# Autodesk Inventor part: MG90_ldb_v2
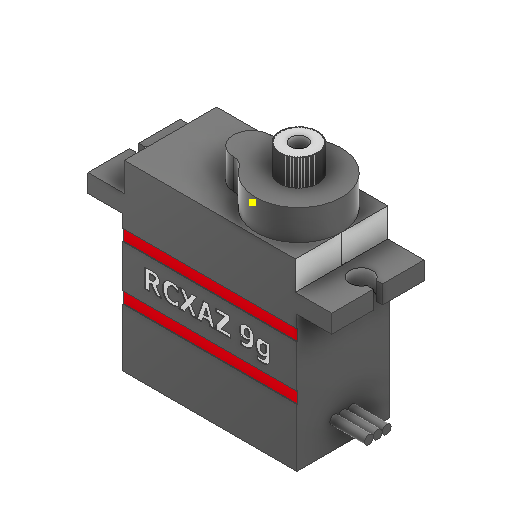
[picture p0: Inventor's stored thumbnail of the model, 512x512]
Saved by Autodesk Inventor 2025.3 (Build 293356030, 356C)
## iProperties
Created: 2019-07
Part Number: MG90_ldb_v2
Material: Steel
Document SubType Name: Modeling
Designer: Ryzen5700u
Density: 7.85 g/cm^3
Appearance: Default
Author: Ryzen5700u
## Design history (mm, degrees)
node "Geometria corretta1"
  node "Schizzo8-Invisible"
node "Solido1"
sketch "Schizzo2-Invisible"
sketch "Schizzo9-Invisible"
node "Schizzo11-Invisible"
node "Schizzo12-Invisible"
node "Schizzo6-Invisible"
sketch "Schizzo10-Invisible"
node "Schizzo7-Invisible"
node "Schizzo13-Invisible"
sketch "Schizzo1"
  geometry: L1 (23, -4.915)-(23, 0) reference; L2 (23, 0)-(0, 0) reference; L3 (0, 0)-(0, -12.5) reference; L4 (0, -12.5)-(23, -12.5) reference; L5 (23, -12.5)-(23, -7.585) reference; A1 r 6 centre (17.15, -6.25) between (23, -4.915) and (11.734, -3.666) reference; A2 r 6 centre (17.15, -6.25) between (11.734, -8.834) and (23, -7.585) reference; A3 r 2.7 centre (10.95, -6.25) between (11.734, -3.666) and (11.734, -8.834) reference; 1 further point
extrude "Estrusione1" join sketch "Schizzo1" distance "d0" = 1.3; taper "d1" = 0 deg
sketch "Schizzo2"
  geometry: L1 (4.6, 0)-(4.6, -12.5) reference; L2 (4.6, 0)-(0, 0) reference; L3 (0, 0)-(0, -5.65) reference; L4 (1.4, -5.65)-(0, -5.65) reference; L5 (1.4, -6.85)-(0, -6.85) reference; L6 (0, -6.85)-(0, -12.5) reference; L7 (4.6, -12.5)-(0, -12.5) reference; L8 (27.6, -12.5)-(27.6, 0) reference; L9 (27.6, -12.5)-(32.2, -12.5) reference; L10 (32.2, -12.5)-(32.2, -6.85) reference; L11 (30.8, -6.85)-(32.2, -6.85) reference; L12 (30.8, -5.65)-(32.2, -5.65) reference; L13 (32.2, -5.65)-(32.2, 0) reference; L14 (27.6, 0)-(32.2, 0) reference; A1 r 1 centre (2.2, -6.25) between (1.4, -6.85) and (1.4, -5.65) reference; A2 r 1 centre (30, -6.25) between (30.8, -5.65) and (30.8, -6.85) reference; 1 further point
extrude "Estrusione2" cut sketch "Schizzo2" distance "d5" = 1.8; taper "d6" = 0 deg
sketch "Schizzo3"
  geometry: L1 (4.6, 0)-(4.6, -12.5) reference; L2 (4.6, 0)-(0, 0) reference; L3 (0, 0)-(0, -5.65) reference; L4 (0, -5.65)-(1.4, -5.65) reference; L5 (1.4, -6.85)-(0, -6.85) reference; L6 (0, -6.85)-(0, -12.5) reference; L7 (4.6, -12.5)-(0, -12.5) reference; L8 (27.6, -12.5)-(27.6, 0) reference; L9 (27.6, -12.5)-(32.2, -12.5) reference; L10 (32.2, -12.5)-(32.2, -6.85) reference; L11 (32.2, -6.85)-(30.8, -6.85) reference; L12 (30.8, -5.65)-(32.2, -5.65) reference; L13 (32.2, -5.65)-(32.2, 0) reference; L14 (27.6, 0)-(32.2, 0) reference; A1 r 1 centre (2.2, -6.25) between (1.4, -6.85) and (1.4, -5.65) reference; A2 r 1 centre (30, -6.25) between (30.8, -5.65) and (30.8, -6.85) reference; 1 further point
extrude "Estrusione3" join sketch "Schizzo3" distance "d7" = 1.5; taper "d8" = 0 deg
sketch "Schizzo4"
  geometry: L1 (-0.548, -2.337)-(-0.45, -2.358) reference; L2 (-0.569, -2.434)-(-0.548, -2.337) reference; L3 (-0.694, -2.298)-(-0.725, -2.393) reference; L4 (-0.789, -2.267)-(-0.694, -2.298) reference; L5 (-0.82, -2.362)-(-0.789, -2.267) reference; L6 (-0.93, -2.213)-(-0.971, -2.304) reference; L7 (-1.022, -2.172)-(-0.93, -2.213) reference; L8 (-1.062, -2.263)-(-1.022, -2.172) reference; L9 (-1.157, -2.103)-(-1.206, -2.19) reference; L10 (-1.243, -2.053)-(-1.157, -2.103) reference; L11 (-1.293, -2.14)-(-1.243, -2.053) reference; L12 (-1.37, -1.971)-(-1.429, -2.052) reference; L13 (-1.451, -1.912)-(-1.37, -1.971) reference; L14 (-1.51, -1.993)-(-1.451, -1.912) reference; L15 (-1.569, -1.817)-(-1.635, -1.891) reference; L16 (-1.643, -1.75)-(-1.569, -1.817) reference; L17 (-1.71, -1.824)-(-1.643, -1.75) reference; L18 (-1.75, -1.643)-(-1.824, -1.71) reference; L19 (-1.817, -1.569)-(-1.75, -1.643) reference; L20 (-1.891, -1.635)-(-1.817, -1.569) reference; L21 (-1.912, -1.451)-(-1.993, -1.51) reference; L22 (-1.971, -1.37)-(-1.912, -1.451) reference; L23 (-2.052, -1.429)-(-1.971, -1.37) reference; L24 (-2.053, -1.243)-(-2.14, -1.293) reference; L25 (-2.103, -1.157)-(-2.053, -1.243) reference; L26 (-2.19, -1.206)-(-2.103, -1.157) reference; L27 (-2.172, -1.022)-(-2.263, -1.062) reference; L28 (-2.213, -0.93)-(-2.172, -1.022) reference; L29 (-2.304, -0.971)-(-2.213, -0.93) reference; L30 (-2.267, -0.789)-(-2.362, -0.82) reference; L31 (-2.298, -0.694)-(-2.267, -0.789) reference; L32 (-2.393, -0.725)-(-2.298, -0.694) reference; L33 (-2.337, -0.548)-(-2.434, -0.569) reference; L34 (-2.358, -0.45)-(-2.337, -0.548) reference; L35 (-2.455, -0.471)-(-2.358, -0.45) reference; L36 (-2.382, -0.301)-(-2.481, -0.311) reference; L37 (-2.392, -0.201)-(-2.382, -0.301) reference; L38 (-2.491, -0.212)-(-2.392, -0.201) reference; L39 (-2.4, -0.05)-(-2.499, -0.05) reference; L40 (-2.4, 0.05)-(-2.4, -0.05) reference; L41 (-2.499, 0.05)-(-2.4, 0.05) reference; L42 (-2.392, 0.201)-(-2.491, 0.212) reference; L43 (-2.382, 0.301)-(-2.392, 0.201) reference; L44 (-2.481, 0.311)-(-2.382, 0.301) reference; L45 (-2.358, 0.45)-(-2.455, 0.471) reference; L46 (-2.337, 0.548)-(-2.358, 0.45) reference; L47 (-2.434, 0.569)-(-2.337, 0.548) reference; L48 (-2.298, 0.694)-(-2.393, 0.725) reference; L49 (-2.267, 0.789)-(-2.298, 0.694) reference; L50 (-2.362, 0.82)-(-2.267, 0.789) reference; L51 (-2.213, 0.93)-(-2.304, 0.971) reference; L52 (-2.172, 1.022)-(-2.213, 0.93) reference; L53 (-2.263, 1.062)-(-2.172, 1.022) reference; L54 (-2.103, 1.157)-(-2.19, 1.206) reference; L55 (-2.053, 1.243)-(-2.103, 1.157) reference; L56 (-2.14, 1.293)-(-2.053, 1.243) reference; L57 (-1.971, 1.37)-(-2.052, 1.429) reference; L58 (-1.912, 1.451)-(-1.971, 1.37) reference; L59 (-1.993, 1.51)-(-1.912, 1.451) reference; L60 (-1.817, 1.569)-(-1.891, 1.635) reference; L61 (-1.75, 1.643)-(-1.817, 1.569) reference; L62 (-1.824, 1.71)-(-1.75, 1.643) reference; L63 (-1.643, 1.75)-(-1.71, 1.824) reference; L64 (-1.569, 1.817)-(-1.643, 1.75) reference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; A1 r 6 centre (0, 0) between (-5.416, -2.584) and (-5.416, 2.584) reference; A2 r 2.7 centre (-6.2, 0) between (-5.416, 2.584) and (-5.416, -2.584) reference; A3 r 2.5 centre (0, 0) between (-0.725, -2.393) and (-0.569, -2.434) reference; A4 r 2.5 centre (0, 0) between (-0.971, -2.304) and (-0.82, -2.362) reference; A5 r 2.5 centre (0, 0) between (-1.206, -2.19) and (-1.062, -2.263) reference; A6 r 2.5 centre (0, 0) between (-1.429, -2.052) and (-1.293, -2.14) reference; A7 r 2.5 centre (0, 0) between (-1.635, -1.891) and (-1.51, -1.993) reference; A8 r 2.5 centre (0, 0) between (-1.824, -1.71) and (-1.71, -1.824) reference; A9 r 2.5 centre (0, 0) between (-1.993, -1.51) and (-1.891, -1.635) reference; A10 r 2.5 centre (0, 0) between (-2.14, -1.293) and (-2.052, -1.429) reference; A11 r 2.5 centre (0, 0) between (-2.263, -1.062) and (-2.19, -1.206) reference; A12 r 2.5 centre (0, 0) between (-2.362, -0.82) and (-2.304, -0.971) reference; A13 r 2.5 centre (0, 0) between (-2.434, -0.569) and (-2.393, -0.725) reference; A14 r 2.5 centre (0, 0) between (-2.481, -0.311) and (-2.455, -0.471) reference; A15 r 2.5 centre (0, 0) between (-2.499, -0.05) and (-2.491, -0.212) reference; A16 r 2.5 centre (0, 0) between (-2.491, 0.212) and (-2.499, 0.05) reference; A17 r 2.5 centre (0, 0) between (-2.455, 0.471) and (-2.481, 0.311) reference; A18 r 2.5 centre (0, 0) between (-2.393, 0.725) and (-2.434, 0.569) reference; A19 r 2.5 centre (0, 0) between (-2.304, 0.971) and (-2.362, 0.82) reference; A20 r 2.5 centre (0, 0) between (-2.19, 1.206) and (-2.263, 1.062) reference; A21 r 2.5 centre (0, 0) between (-2.052, 1.429) and (-2.14, 1.293) reference; A22 r 2.5 centre (0, 0) between (-1.891, 1.635) and (-1.993, 1.51) reference; A23 r 2.5 centre (0, 0) between (-1.71, 1.824) and (-1.824, 1.71) reference; A24 r 2.5 centre (0, 0) between (-1.51, 1.993) and (-1.635, 1.891) reference; A25 r 2.5 centre (0, 0) between (-1.293, 2.14) and (-1.429, 2.052) reference; A26 r 2.5 centre (0, 0) between (-1.062, 2.263) and (-1.206, 2.19) reference; A27 r 2.5 centre (0, 0) between (-0.82, 2.362) and (-0.971, 2.304) reference; A28 r 2.5 centre (0, 0) between (-0.569, 2.434) and (-0.725, 2.393) reference; A29 r 2.5 centre (0, 0) between (-0.311, 2.481) and (-0.471, 2.455) reference; A30 r 2.5 centre (0, 0) between (-0.05, 2.499) and (-0.212, 2.491) reference; A31 r 2.5 centre (0, 0) between (0.212, 2.491) and (0.05, 2.499) reference; A32 r 2.5 centre (0, 0) between (0.471, 2.455) and (0.311, 2.481) reference; A33 r 2.5 centre (0, 0) between (0.725, 2.393) and (0.569, 2.434) reference; A34 r 2.5 centre (0, 0) between (0.971, 2.304) and (0.82, 2.362) reference; A35 r 2.5 centre (0, 0) between (1.206, 2.19) and (1.062, 2.263) reference; A36 r 2.5 centre (0, 0) between (1.429, 2.052) and (1.293, 2.14) reference; A37 r 2.5 centre (0, 0) between (1.635, 1.891) and (1.51, 1.993) reference; A38 r 2.5 centre (0, 0) between (1.824, 1.71) and (1.71, 1.824) reference; A39 r 2.5 centre (0, 0) between (1.993, 1.51) and (1.891, 1.635) reference; A40 r 2.5 centre (0, 0) between (2.14, 1.293) and (2.052, 1.429) reference; A41 r 2.5 centre (0, 0) between (2.263, 1.062) and (2.19, 1.206) reference; A42 r 2.5 centre (0, 0) between (2.362, 0.82) and (2.304, 0.971) reference; A43 r 2.5 centre (0, 0) between (2.434, 0.569) and (2.393, 0.725) reference; A44 r 2.5 centre (0, 0) between (2.481, 0.311) and (2.455, 0.471) reference; A45 r 2.5 centre (0, 0) between (2.499, 0.05) and (2.491, 0.212) reference; A46 r 2.5 centre (0, 0) between (2.491, -0.212) and (2.499, -0.05) reference; A47 r 2.5 centre (0, 0) between (2.455, -0.471) and (2.481, -0.311) reference; A48 r 2.5 centre (0, 0) between (2.393, -0.725) and (2.434, -0.569) reference; A49 r 2.5 centre (0, 0) between (2.304, -0.971) and (2.362, -0.82) reference; A50 r 2.5 centre (0, 0) between (2.19, -1.206) and (2.263, -1.062) reference; A51 r 2.5 centre (0, 0) between (2.052, -1.429) and (2.14, -1.293) reference; A52 r 2.5 centre (0, 0) between (1.891, -1.635) and (1.993, -1.51) reference; A53 r 2.5 centre (0, 0) between (1.71, -1.824) and (1.824, -1.71) reference; A54 r 2.5 centre (0, 0) between (1.51, -1.993) and (1.635, -1.891) reference; A55 r 2.5 centre (0, 0) between (1.293, -2.14) and (1.429, -2.052) reference; A56 r 2.5 centre (0, 0) between (1.062, -2.263) and (1.206, -2.19) reference; A57 r 2.5 centre (0, 0) between (0.82, -2.362) and (0.971, -2.304) reference; A58 r 2.5 centre (0, 0) between (0.569, -2.434) and (0.725, -2.393) reference; A59 r 2.5 centre (0, 0) between (0.311, -2.481) and (0.471, -2.455) reference; A60 r 2.5 centre (0, 0) between (0.05, -2.499) and (0.212, -2.491) reference; A61 r 2.5 centre (0, 0) between (-0.212, -2.491) and (-0.05, -2.499) reference; A62 r 2.5 centre (0, 0) between (-0.471, -2.455) and (-0.311, -2.481) reference; 1 further point
extrude "Estrusione4" cut sketch "Schizzo4" distance "d9" = 0.7; taper "d10" = 0 deg
sketch "Schizzo5"
  geometry: C1 r 1.1 at (0, 0) reference; C2 r 3.334 at (0, 0); 1 further point
  constraints: 1 centre point, 1 coincident
extrude "Estrusione5" cut sketch "Schizzo5" distance "d11" = 1.2; taper "d12" = 0 deg
node "Modifica diretta1"
node "Modifica diretta2"
sketch "Schizzo6"
  geometry: L1 (23, 0)-(23, 17.2) reference; L2 (0, 17.2)-(0, 0) reference; L3 (23, 5.728)-(0, 5.728); L4 (0, 5.728)-(0, 17.02); L5 (0, 17.02)-(23, 17.02); L6 (23, 17.02)-(23, 5.728); 3 further points
  constraints: 8 end point, 2 parallel, 2 point on line, 1 horizontal, 1 perpendicular
extrude "Estrusione6" cut sketch "Schizzo6" distance "d19" = 0.1; taper "d20" = 0 deg
sketch "Schizzo8"
  geometry: L1 (21.235, 0)-(0, 0) reference; L2 (21.235, 12.123)-(21.235, 0) reference; L3 (0, 12.123)-(21.235, 12.123) reference; L4 (0, 0)-(0, 12.123) reference; 1 further point
extrude "Estrusione7" join sketch "Schizzo8" stored distance "d21" = 10; taper "d22" = 0 deg
sketch "Schizzo9"
  geometry: L1 (0, 5.728)-(0, 17.02) reference; L2 (23, 5.728)-(0, 5.728) reference; L3 (23, 17.02)-(23, 5.728) reference; L4 (0, 17.02)-(23, 17.02) reference; 1 further point
extrude "Estrusione8" join sketch "Schizzo9" stored distance "d23" = 10; taper "d24" = 0 deg
sketch "Schizzo10"
  geometry: L1 (23, 0)-(0, 0) reference; L2 (23, 12.5)-(23, 0) reference; L3 (0, 12.5)-(23, 12.5) reference; L4 (0, 0)-(0, 12.5) reference; L5 (-2.4, 6.25)-(30.242, 6.25); L6 (-6.338, 12.35)-(30.57, 12.35); L7 (30.57, 12.35)-(30.57, 0.15); L8 (30.57, 0.15)-(-6.338, 0.15); L9 (-6.338, 0.15)-(-6.338, 12.35); L10 (-4.6, 6.85)-(-3.2, 6.85) reference; L11 (-3.2, 5.65)-(-4.6, 5.65) reference; L12 (-4.6, 5.65)-(-4.6, 0) reference; L13 (-4.6, 0)-(0, 0) reference; L14 (0, 12.5)-(0, 0) reference; L15 (0, 12.5)-(-4.6, 12.5) reference; L16 (-4.6, 12.5)-(-4.6, 6.85) reference; L17 (27.6, 5.65)-(26.2, 5.65) reference; L18 (26.2, 6.85)-(27.6, 6.85) reference; L19 (27.6, 6.85)-(27.6, 12.5) reference; L20 (27.6, 12.5)-(23, 12.5) reference; L21 (23, 0)-(23, 12.5) reference; L22 (23, 0)-(27.6, 0) reference; L23 (27.6, 0)-(27.6, 5.65) reference; A1 r 1 centre (-2.4, 6.25) between (-3.2, 5.65) and (-3.2, 6.85) reference; A2 r 1 centre (-2.4, 6.25) between (-3.2, 5.65) and (-3.2, 6.85) reference; A3 r 1 centre (25.4, 6.25) between (26.2, 6.85) and (26.2, 5.65) reference; 13 further points
  constraints: 10 end point, 2 horizontal, 2 parallel, 1 perpendicular, 1 other
  dimensions: "d28" = 12.2 distance of L8.end L6.start
extrude "Estrusione9" cut sketch "Schizzo10" extent not by distance; stored distance "d29" = 0; taper "d30" = 0 deg
sketch "Schizzo11"
  geometry: L1 (-0.569, -2.434)-(-0.548, -2.337) reference; L2 (-0.694, -2.298)-(-0.725, -2.393) reference; L3 (-0.789, -2.267)-(-0.694, -2.298) reference; L4 (-0.82, -2.362)-(-0.789, -2.267) reference; L5 (-0.93, -2.213)-(-0.971, -2.304) reference; L6 (-1.022, -2.172)-(-0.93, -2.213) reference; L7 (-1.062, -2.263)-(-1.022, -2.172) reference; L8 (-1.157, -2.103)-(-1.206, -2.19) reference; L9 (-1.243, -2.053)-(-1.157, -2.103) reference; L10 (-1.293, -2.14)-(-1.243, -2.053) reference; L11 (-1.37, -1.971)-(-1.429, -2.052) reference; L12 (-1.451, -1.912)-(-1.37, -1.971) reference; L13 (-1.51, -1.993)-(-1.451, -1.912) reference; L14 (-1.569, -1.817)-(-1.635, -1.891) reference; L15 (-1.643, -1.75)-(-1.569, -1.817) reference; L16 (-1.71, -1.824)-(-1.643, -1.75) reference; L17 (-1.75, -1.643)-(-1.824, -1.71) reference; L18 (-1.817, -1.569)-(-1.75, -1.643) reference; L19 (-1.891, -1.635)-(-1.817, -1.569) reference; L20 (-1.912, -1.451)-(-1.993, -1.51) reference; L21 (-1.971, -1.37)-(-1.912, -1.451) reference; L22 (-2.052, -1.429)-(-1.971, -1.37) reference; L23 (-2.053, -1.243)-(-2.14, -1.293) reference; L24 (-2.103, -1.157)-(-2.053, -1.243) reference; L25 (-2.19, -1.206)-(-2.103, -1.157) reference; L26 (-2.172, -1.022)-(-2.263, -1.062) reference; L27 (-2.213, -0.93)-(-2.172, -1.022) reference; L28 (-2.304, -0.971)-(-2.213, -0.93) reference; L29 (-2.267, -0.789)-(-2.362, -0.82) reference; L30 (-2.298, -0.694)-(-2.267, -0.789) reference; L31 (-2.393, -0.725)-(-2.298, -0.694) reference; L32 (-2.337, -0.548)-(-2.434, -0.569) reference; L33 (-2.358, -0.45)-(-2.337, -0.548) reference; L34 (-2.455, -0.471)-(-2.358, -0.45) reference; L35 (-2.382, -0.301)-(-2.481, -0.311) reference; L36 (-2.392, -0.201)-(-2.382, -0.301) reference; L37 (-2.491, -0.212)-(-2.392, -0.201) reference; L38 (-2.4, -0.05)-(-2.499, -0.05) reference; L39 (-2.4, 0.05)-(-2.4, -0.05) reference; L40 (-2.499, 0.05)-(-2.4, 0.05) reference; L41 (-2.392, 0.201)-(-2.491, 0.212) reference; L42 (-2.382, 0.301)-(-2.392, 0.201) reference; L43 (-2.481, 0.311)-(-2.382, 0.301) reference; L44 (-2.358, 0.45)-(-2.455, 0.471) reference; L45 (-2.337, 0.548)-(-2.358, 0.45) reference; L46 (-2.434, 0.569)-(-2.337, 0.548) reference; L47 (-2.298, 0.694)-(-2.393, 0.725) reference; L48 (-2.267, 0.789)-(-2.298, 0.694) reference; L49 (-2.362, 0.82)-(-2.267, 0.789) reference; L50 (-2.213, 0.93)-(-2.304, 0.971) reference; L51 (-2.172, 1.022)-(-2.213, 0.93) reference; L52 (-2.263, 1.062)-(-2.172, 1.022) reference; L53 (-2.103, 1.157)-(-2.19, 1.206) reference; L54 (-2.053, 1.243)-(-2.103, 1.157) reference; L55 (-2.14, 1.293)-(-2.053, 1.243) reference; L56 (-1.971, 1.37)-(-2.052, 1.429) reference; L57 (-1.912, 1.451)-(-1.971, 1.37) reference; L58 (-1.993, 1.51)-(-1.912, 1.451) reference; L59 (-1.817, 1.569)-(-1.891, 1.635) reference; L60 (-1.75, 1.643)-(-1.817, 1.569) reference; L61 (-1.824, 1.71)-(-1.75, 1.643) reference; L62 (-1.643, 1.75)-(-1.71, 1.824) reference; L63 (-1.569, 1.817)-(-1.643, 1.75) reference; L64 (-1.635, 1.891)-(-1.569, 1.817) reference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; C1 r 1.1 at (0, 0) reference; C2 r 5.65 at (0, 0); A1 r 2.7 centre (-6.2, 0) between (-5.416, 2.584) and (-5.416, -2.584) reference; A2 r 6 centre (0, 0) between (-5.416, -2.584) and (-5.416, 2.584) reference; A3 r 2.5 centre (0, 0) between (-0.725, -2.393) and (-0.569, -2.434) reference; A4 r 2.5 centre (0, 0) between (-0.971, -2.304) and (-0.82, -2.362) reference; A5 r 2.5 centre (0, 0) between (-1.206, -2.19) and (-1.062, -2.263) reference; A6 r 2.5 centre (0, 0) between (-1.429, -2.052) and (-1.293, -2.14) reference; A7 r 2.5 centre (0, 0) between (-1.635, -1.891) and (-1.51, -1.993) reference; A8 r 2.5 centre (0, 0) between (-1.824, -1.71) and (-1.71, -1.824) reference; A9 r 2.5 centre (0, 0) between (-1.993, -1.51) and (-1.891, -1.635) reference; A10 r 2.5 centre (0, 0) between (-2.14, -1.293) and (-2.052, -1.429) reference; A11 r 2.5 centre (0, 0) between (-2.263, -1.062) and (-2.19, -1.206) reference; A12 r 2.5 centre (0, 0) between (-2.362, -0.82) and (-2.304, -0.971) reference; A13 r 2.5 centre (0, 0) between (-2.434, -0.569) and (-2.393, -0.725) reference; A14 r 2.5 centre (0, 0) between (-2.481, -0.311) and (-2.455, -0.471) reference; A15 r 2.5 centre (0, 0) between (-2.499, -0.05) and (-2.491, -0.212) reference; A16 r 2.5 centre (0, 0) between (-2.491, 0.212) and (-2.499, 0.05) reference; A17 r 2.5 centre (0, 0) between (-2.455, 0.471) and (-2.481, 0.311) reference; A18 r 2.5 centre (0, 0) between (-2.393, 0.725) and (-2.434, 0.569) reference; A19 r 2.5 centre (0, 0) between (-2.304, 0.971) and (-2.362, 0.82) reference; A20 r 2.5 centre (0, 0) between (-2.19, 1.206) and (-2.263, 1.062) reference; A21 r 2.5 centre (0, 0) between (-2.052, 1.429) and (-2.14, 1.293) reference; A22 r 2.5 centre (0, 0) between (-1.891, 1.635) and (-1.993, 1.51) reference; A23 r 2.5 centre (0, 0) between (-1.71, 1.824) and (-1.824, 1.71) reference; A24 r 2.5 centre (0, 0) between (-1.51, 1.993) and (-1.635, 1.891) reference; A25 r 2.5 centre (0, 0) between (-1.293, 2.14) and (-1.429, 2.052) reference; A26 r 2.5 centre (0, 0) between (-1.062, 2.263) and (-1.206, 2.19) reference; A27 r 2.5 centre (0, 0) between (-0.82, 2.362) and (-0.971, 2.304) reference; A28 r 2.5 centre (0, 0) between (-0.569, 2.434) and (-0.725, 2.393) reference; A29 r 2.5 centre (0, 0) between (-0.311, 2.481) and (-0.471, 2.455) reference; A30 r 2.5 centre (0, 0) between (-0.05, 2.499) and (-0.212, 2.491) reference; A31 r 2.5 centre (0, 0) between (0.212, 2.491) and (0.05, 2.499) reference; A32 r 2.5 centre (0, 0) between (0.471, 2.455) and (0.311, 2.481) reference; A33 r 2.5 centre (0, 0) between (0.725, 2.393) and (0.569, 2.434) reference; A34 r 2.5 centre (0, 0) between (0.971, 2.304) and (0.82, 2.362) reference; A35 r 2.5 centre (0, 0) between (1.206, 2.19) and (1.062, 2.263) reference; A36 r 2.5 centre (0, 0) between (1.429, 2.052) and (1.293, 2.14) reference; A37 r 2.5 centre (0, 0) between (1.635, 1.891) and (1.51, 1.993) reference; A38 r 2.5 centre (0, 0) between (1.824, 1.71) and (1.71, 1.824) reference; A39 r 2.5 centre (0, 0) between (1.993, 1.51) and (1.891, 1.635) reference; A40 r 2.5 centre (0, 0) between (2.14, 1.293) and (2.052, 1.429) reference; A41 r 2.5 centre (0, 0) between (2.263, 1.062) and (2.19, 1.206) reference; A42 r 2.5 centre (0, 0) between (2.362, 0.82) and (2.304, 0.971) reference; A43 r 2.5 centre (0, 0) between (2.434, 0.569) and (2.393, 0.725) reference; A44 r 2.5 centre (0, 0) between (2.481, 0.311) and (2.455, 0.471) reference; A45 r 2.5 centre (0, 0) between (2.499, 0.05) and (2.491, 0.212) reference; A46 r 2.5 centre (0, 0) between (2.491, -0.212) and (2.499, -0.05) reference; A47 r 2.5 centre (0, 0) between (2.455, -0.471) and (2.481, -0.311) reference; A48 r 2.5 centre (0, 0) between (2.393, -0.725) and (2.434, -0.569) reference; A49 r 2.5 centre (0, 0) between (2.304, -0.971) and (2.362, -0.82) reference; A50 r 2.5 centre (0, 0) between (2.19, -1.206) and (2.263, -1.062) reference; A51 r 2.5 centre (0, 0) between (2.052, -1.429) and (2.14, -1.293) reference; A52 r 2.5 centre (0, 0) between (1.891, -1.635) and (1.993, -1.51) reference; A53 r 2.5 centre (0, 0) between (1.71, -1.824) and (1.824, -1.71) reference; A54 r 2.5 centre (0, 0) between (1.51, -1.993) and (1.635, -1.891) reference; A55 r 2.5 centre (0, 0) between (1.293, -2.14) and (1.429, -2.052) reference; A56 r 2.5 centre (0, 0) between (1.062, -2.263) and (1.206, -2.19) reference; A57 r 2.5 centre (0, 0) between (0.82, -2.362) and (0.971, -2.304) reference; A58 r 2.5 centre (0, 0) between (0.569, -2.434) and (0.725, -2.393) reference; A59 r 2.5 centre (0, 0) between (0.311, -2.481) and (0.471, -2.455) reference; A60 r 2.5 centre (0, 0) between (0.05, -2.499) and (0.212, -2.491) reference; A61 r 2.5 centre (0, 0) between (-0.212, -2.491) and (-0.05, -2.499) reference; A62 r 2.5 centre (0, 0) between (-0.471, -2.455) and (-0.311, -2.481) reference; A63 r 1 centre (-19.55, 0) between (-20.35, -0.6) and (-20.35, 0.6) reference; 10 further points
  constraints: 12 end point, 2 coincident, 2 horizontal, 2 parallel, 2 point on line, 1 centre point, 1 midpoint, 1 perpendicular, 3 other
  dimensions: "d31" = 11.3 diameter of C2; "d32" = 14.5 distance of point (5.85, 0) point (-8.65, 0)
extrude "Estrusione10" cut sketch "Schizzo11" stored distance "d33" = 10; taper "d34" = 0 deg
fillet "Raccordo1" dims "d35" = 2
sketch "Schizzo12"
  geometry: L1 (0, 0)-(23, 0) reference; L2 (23, 12.2)-(23, 0) reference; L3 (23, 12.2)-(0, 12.2) reference; L4 (0, 0)-(0, 12.2) reference; 1 further point
extrude "Estrusione11" join sketch "Schizzo12" distance "d39" = 0.4; taper "d40" = 0 deg
sketch "Schizzo13"
  geometry: L1 (4.6, -0.15)-(0, -0.15) reference; L2 (0, -5.65)-(0, -0.15) reference; L3 (1.4, -5.65)-(0, -5.65) reference; L4 (0, -6.85)-(1.4, -6.85) reference; L5 (0, -12.35)-(0, -6.85) reference; L6 (0, -12.35)-(4.6, -12.35) reference; L7 (4.6, -0.15)-(4.6, -12.35) reference; L8 (32.2, -0.15)-(27.6, -0.15) reference; L9 (27.6, -12.35)-(27.6, -0.15) reference; L10 (27.6, -12.35)-(32.2, -12.35) reference; L11 (32.2, -6.85)-(32.2, -12.35) reference; L12 (30.8, -6.85)-(32.2, -6.85) reference; L13 (32.2, -5.65)-(30.8, -5.65) reference; L14 (32.2, -0.15)-(32.2, -5.65) reference; A1 r 1 centre (2.2, -6.25) between (1.4, -6.85) and (1.4, -5.65) reference; A2 r 1 centre (30, -6.25) between (30.8, -5.65) and (30.8, -6.85) reference; 1 further point
extrude "Estrusione12" join sketch "Schizzo13" distance "d44" = 0.3; taper "d45" = 0 deg
sketch "Schizzo14"
  geometry: L1 (0, -12.35)-(4.6, -12.35) reference; L2 (4.6, -0.15)-(4.6, -12.35) reference; L3 (4.6, -0.15)-(0, -0.15) reference; L4 (0, -0.15)-(0, -5.65) reference; L5 (0, -5.65)-(1.4, -5.65) reference; L6 (1.4, -6.85)-(0, -6.85) reference; L7 (0, -6.85)-(0, -12.35) reference; L8 (27.6, -12.35)-(32.2, -12.35) reference; L9 (32.2, -12.35)-(32.2, -6.85) reference; L10 (32.2, -6.85)-(30.8, -6.85) reference; L11 (30.8, -5.65)-(32.2, -5.65) reference; L12 (32.2, -5.65)-(32.2, -0.15) reference; L13 (32.2, -0.15)-(27.6, -0.15) reference; L14 (27.6, -12.35)-(27.6, -0.15) reference; A1 r 1 centre (2.2, -6.25) between (1.4, -6.85) and (1.4, -5.65) reference; A2 r 1 centre (30, -6.25) between (30.8, -5.65) and (30.8, -6.85) reference; 1 further point
extrude "Estrusione13" cut sketch "Schizzo14" distance "d49" = 0.4; taper "d50" = 0 deg
sketch "Schizzo15"
  geometry: L1 (23, -0.15)-(0, -0.15) reference; L2 (0, -0.15)-(0, -12.35) reference; L3 (0, -12.35)-(23, -12.35) reference; L4 (23, -12.35)-(23, -7.585) reference; L5 (23, -4.915)-(23, -0.15) reference; L6 (23, -7.585)-(23, -4.915); A1 r 2 centre (10.927, -1.8) between (10.938, -3.8) and (12.554, -2.963) reference; A2 r 5.65 centre (17.15, -6.25) between (12.554, -9.537) and (12.554, -2.963) reference; A3 r 2 centre (10.927, -10.7) between (12.554, -9.537) and (10.938, -8.7) reference; A4 r 2.45 centre (10.95, -6.25) between (10.938, -3.8) and (10.938, -8.7) reference; A5 r 6 centre (17.15, -6.25) between (23, -7.585) and (23, -4.915) reference; 1 further point
  constraints: 2 end point, 1 vertical
extrude "Estrusione14" cut sketch "Schizzo15" stored distance "d51" = 0.4; taper "d52" = 0 deg
sketch "Schizzo16"
  geometry: L1 (0, -24.2)-(0, -6.2) reference; L2 (23, -6.2)-(23, -24.2) reference; L3 (0, -7.885)-(23, -7.885); L4 (23, -7.885)-(23, -9.385); L5 (23, -9.385)-(0, -9.385); L6 (0, -9.385)-(0, -7.885); L7 (0, -15.029)-(23, -15.029); L8 (23, -15.029)-(23, -16.529); L9 (23, -16.529)-(0, -16.529); L10 (0, -16.529)-(0, -15.029); 6 further points
  constraints: 16 end point, 4 parallel, 4 point on line, 2 horizontal, 2 perpendicular
  dimensions: "d53" = 1.5 distance between parallel lines of L5 L3; "d54" = 1.5 distance between parallel lines of L9 L7
extrude "Estrusione15" cut sketch "Schizzo16" distance "d55" = 0.1; taper "d56" = 0 deg
sketch "Schizzo17"
  geometry: 1 further point
sketch "Schizzo18"
  geometry: L1 (2.634, 4.211)-(26.434, 4.211); L2 (26.434, 4.211)-(26.434, -0.353); L3 (26.434, -0.353)-(2.634, -0.353); L4 (2.634, -0.353)-(2.634, 4.211); 1 further point
  constraints: 2 other
extrude "Estrusione16" cut sketch "Schizzo18" distance "d57" = 0.1; taper "d58" = 0 deg
sketch "Schizzo19"
  geometry: L1 (4.6, -0.15)-(4.6, -12.35) reference; L2 (4.6, -0.15)-(0, -0.15) reference; L3 (0, -0.15)-(0, -5.65) reference; L4 (0, -5.65)-(1.4, -5.65) reference; L5 (1.4, -6.85)-(0, -6.85) reference; L6 (0, -6.85)-(0, -12.35) reference; L7 (0, -12.35)-(4.6, -12.35) reference; L8 (27.6, -12.35)-(27.6, -0.15) reference; L9 (27.6, -12.35)-(32.2, -12.35) reference; L10 (32.2, -12.35)-(32.2, -6.85) reference; L11 (32.2, -6.85)-(30.8, -6.85) reference; L12 (30.8, -5.65)-(32.2, -5.65) reference; L13 (32.2, -5.65)-(32.2, -0.15) reference; L14 (32.2, -0.15)-(27.6, -0.15) reference; C1 r 1.5 at (2.2, -6.25); C2 r 1.5 at (30, -6.25); A1 r 1 centre (2.2, -6.25) between (1.4, -6.85) and (1.4, -5.65) reference; A2 r 1 centre (30, -6.25) between (30.8, -5.65) and (30.8, -6.85) reference; 5 further points
  constraints: 2 centre point, 2 coincident
  dimensions: "d62" = 3 diameter of C1; "d63" = 3 diameter of C2
  node "Linea chiusa proiettata20"
  node "Linea chiusa proiettata21"
sketch "Schizzo20"
  geometry: L1 (23, -12.35)-(23, -0.15) reference; L2 (23, -0.15)-(0, -0.15) reference; L3 (0, -0.15)-(0, -12.35) reference; L4 (0, -12.35)-(23, -12.35) reference; L5 (0.2, -0.35)-(22.8, -0.35); L6 (22.8, -0.15)-(22.8, -4.937); L7 (22.8, -7.563)-(22.8, -12.35); L8 (22.8, -12.15)-(0.2, -12.15); L9 (0.2, -12.35)-(0.2, -0.15); L10 (22.8, -4.937)-(22.8, -7.563); A1 r 2 centre (10.927, -1.8) between (10.938, -3.8) and (12.554, -2.963) reference; A2 r 5.65 centre (17.15, -6.25) between (12.554, -9.537) and (12.554, -2.963) reference; A3 r 2 centre (10.927, -10.7) between (12.554, -9.537) and (10.938, -8.7) reference; A4 r 2.45 centre (10.95, -6.25) between (10.938, -3.8) and (10.938, -8.7) reference; A5 r 5.8 centre (17.15, -6.25) between (22.8, -7.563) and (22.8, -4.937); 2 further points
  constraints: 12 end point, 8 point on line, 2 point on circle, 1 centre point, 1 collinear
  dimensions: "d59" = 0.2 distance between parallel lines of L2 L5
extrude "Estrusione17" cut sketch "Schizzo20" stored distance "d60" = 0.1; taper "d61" = 0 deg
extrude "Estrusione18" cut sketch "Schizzo19" distance "d64" = 10; taper "d65" = 0 deg
node "Solido2"
node "Linea chiusa proiettata1"
node "Linea chiusa proiettata2"
node "Linea chiusa proiettata3"
node "Linea chiusa proiettata4"
node "Linea chiusa proiettata5"
node "Linea chiusa proiettata6"
node "Linea chiusa proiettata7"
node "Linea chiusa proiettata8"
node "Linea chiusa proiettata9"
node "Linea chiusa proiettata10"
node "Linea chiusa proiettata11"
node "Linea chiusa proiettata12"
node "Linea chiusa proiettata13"
node "Linea chiusa proiettata14"
node "Linea chiusa proiettata15"
node "Linea chiusa proiettata16"
node "Linea chiusa proiettata17"
node "Linea chiusa proiettata18"
node "Linea chiusa proiettata19"
feature "Sposta1" dims "d13" = -1.5
feature "Sposta2" dims "d16" = -1.5
other parameters: "d14" = 0, "d15" = 0, "d17" = 0, "d18" = 0
